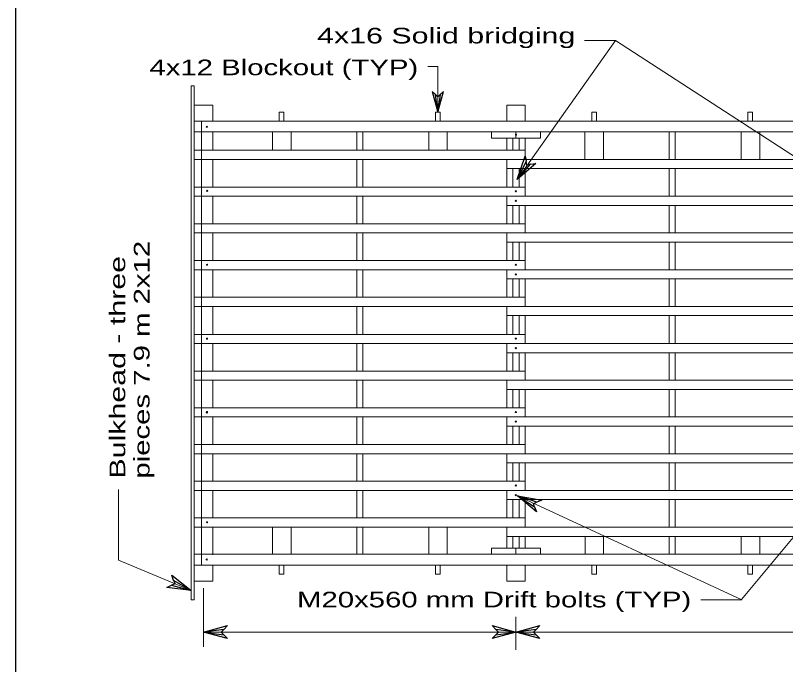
# Model space of a CAD drawing. Extents: x 13426 to 15509, y -9298 to -5111.
# Drawn here: x 15181.1 to 15245.4, y -5476.4 to -5422.2 of the extents above; entities that cross this region are included whole.
import ezdxf
from ezdxf.enums import TextEntityAlignment as Align

# ---------------------------------------------------------------- set-up
doc = ezdxf.new("R2010")
doc.units = 0
doc.header["$LTSCALE"] = 0.52
for name, color, linetype, lineweight in [('1', 7, 'Continuous', 13), ('15', 7, 'Continuous', 13), ('16', 7, 'Continuous', 25), ('2', 7, 'Continuous', 25), ('20', 7, 'Continuous', 13), ('3', 7, 'Continuous', 25), ('30', 7, 'Continuous', 25), ('4', 7, 'Continuous', 13), ('5', 7, 'Continuous', 25), ('6', 7, 'Continuous', 13)]:
    doc.layers.add(name, color=color, linetype=linetype, lineweight=lineweight)
doc.layers.add('19', color=7, linetype='Continuous')

msp = doc.modelspace()

# ---------------------------------------------------------------- linework, layer by layer
at = {"layer": '1'}
for p, q in [((15196.054, -5429.698), (15197.588, -5429.698)), ((15197.588, -5431.049), (15197.588, -5429.698)), ((15222.133, -5431.049), (15222.133, -5429.698)), ((15203.149, -5430.288), (15203.533, -5430.288)), ((15203.149, -5430.288), (15203.149, -5431.05)), ((15203.533, -5430.288), (15203.533, -5431.05)), ((15216.189, -5430.288), (15216.572, -5430.288)), ((15216.189, -5430.288), (15216.189, -5431.05)), ((15216.572, -5430.288), (15216.572, -5431.05)), ((15229.229, -5430.288), (15229.612, -5430.288)), ((15229.229, -5430.288), (15229.229, -5431.05)), ((15229.612, -5430.288), (15229.612, -5431.05)), ((15242.268, -5430.288), (15242.651, -5430.288)), ((15242.268, -5430.288), (15242.268, -5431.05)), ((15242.651, -5430.288), (15242.651, -5431.05)), ((15314.177, -5431.05), (15196.054, -5431.05)), ((15314.177, -5431.944), (15196.054, -5431.944)), ((15197.588, -5431.944), (15197.588, -5433.478)), ((15222.133, -5432.458), (15222.133, -5433.478)), ((15223.667, -5432.458), (15223.667, -5434.245)), ((15197.588, -5434.245), (15197.588, -5436.546)), ((15222.133, -5434.245), (15222.133, -5436.546)), ((15223.667, -5435.012), (15223.667, -5437.313)), ((15197.588, -5437.313), (15197.588, -5439.614)), ((15222.133, -5437.313), (15222.133, -5439.614)), ((15223.667, -5438.08), (15223.667, -5440.381)), ((15197.588, -5440.381), (15197.588, -5442.682)), ((15222.133, -5440.381), (15222.133, -5442.682)), ((15223.667, -5441.148), (15223.667, -5443.45)), ((15197.588, -5443.45), (15197.588, -5445.751)), ((15222.133, -5443.45), (15222.133, -5445.751)), ((15223.667, -5444.217), (15223.667, -5446.518)), ((15197.588, -5446.518), (15197.588, -5448.817)), ((15222.133, -5446.518), (15222.133, -5448.851)), ((15223.667, -5447.285), (15223.667, -5449.618)), ((15197.588, -5449.618), (15197.588, -5451.919)), ((15222.133, -5449.618), (15222.133, -5451.919)), ((15223.667, -5450.385), (15223.667, -5452.686)), ((15197.588, -5452.686), (15197.588, -5454.987)), ((15222.133, -5452.686), (15222.133, -5454.987)), ((15223.667, -5453.453), (15223.667, -5455.754)), ((15197.588, -5455.754), (15197.588, -5458.055)), ((15222.133, -5455.754), (15222.133, -5458.055)), ((15223.667, -5456.521), (15223.667, -5458.822)), ((15197.588, -5458.822), (15197.588, -5461.123)), ((15222.133, -5458.822), (15222.133, -5461.123)), ((15223.667, -5459.589), (15223.667, -5461.89)), ((15197.588, -5461.89), (15197.588, -5464.191)), ((15222.133, -5461.89), (15222.133, -5464.191)), ((15223.667, -5462.657), (15223.667, -5464.958)), ((15197.588, -5464.958), (15197.588, -5467.258)), ((15222.133, -5464.958), (15222.133, -5466.746)), ((15223.667, -5465.725), (15223.667, -5466.746)), ((15314.177, -5467.226), (15196.054, -5467.226)), ((15314.177, -5468.12), (15196.054, -5468.12)), ((15197.588, -5469.462), (15197.588, -5468.12)), ((15203.149, -5468.878), (15203.149, -5468.12)), ((15203.533, -5468.878), (15203.533, -5468.12)), ((15216.189, -5468.878), (15216.189, -5468.12)), ((15216.572, -5468.878), (15216.572, -5468.12)), ((15222.133, -5469.462), (15222.133, -5468.12)), ((15223.667, -5469.462), (15223.667, -5468.12)), ((15229.229, -5468.878), (15229.229, -5468.12)), ((15229.612, -5468.878), (15229.612, -5468.12)), ((15242.268, -5468.878), (15242.268, -5468.12)), ((15242.651, -5468.878), (15242.651, -5468.12)), ((15203.149, -5468.878), (15203.533, -5468.878)), ((15216.572, -5468.878), (15216.189, -5468.878)), ((15229.612, -5468.878), (15229.229, -5468.878)), ((15242.651, -5468.878), (15242.268, -5468.878)), ((15197.588, -5469.462), (15196.054, -5469.462)), ((15223.667, -5469.462), (15222.133, -5469.462))]:
    msp.add_line(p, q, dxfattribs=at)
msp.add_lwpolyline([(15223.667, -5431.049), (15223.667, -5429.698), (15222.133, -5429.698)], dxfattribs=at)
at = {"layer": '15'}
for p, q in [((15231.205, -5424.302), (15248.989, -5435.844)), ((15241.742, -5471.015), (15223.02, -5462.352)), ((15241.735, -5471.01), (15248.887, -5462.38)), ((15196.821, -5470.06), (15196.821, -5474.948)), ((15238.331, -5471.017), (15241.738, -5471.017)), ((15222.9, -5472.443), (15222.9, -5475.217)), ((15196.821, -5473.718), (15222.9, -5473.718))]:
    msp.add_line(p, q, dxfattribs=at)
for points in [[(15228.625, -5424.302), (15231.205, -5424.302), (15222.991, -5435.916)], [(15215.557, -5426.47), (15216.385, -5426.47), (15216.385, -5430.288)], [(15189.721, -5461.808), (15189.721, -5467.701), (15195.799, -5470.256)], [(15222.9, -5473.719), (15248.979, -5473.719), (15274.589, -5473.719)]]:
    msp.add_lwpolyline(points, dxfattribs=at)
at = {"layer": '16'}
for points in [[(15216.194, -5428.823), (15215.912, -5428.553), (15216.385, -5430.288), (15216.859, -5428.553), (15216.576, -5428.823), (15216.385, -5430.288), (15216.194, -5428.823), (15216.385, -5429.014), (15216.576, -5428.823)], [(15224.125, -5434.648), (15224.569, -5434.573), (15222.992, -5435.918), (15223.668, -5433.959), (15223.76, -5434.399), (15222.992, -5435.918), (15224.125, -5434.648), (15223.818, -5434.706), (15223.76, -5434.399)], [(15224.459, -5463.261), (15224.605, -5463.686), (15223.02, -5462.352), (15225.063, -5462.697), (15224.644, -5462.86), (15223.02, -5462.352), (15224.459, -5463.261), (15224.351, -5462.968), (15224.644, -5462.86)], [(15194.329, -5469.399), (15194.167, -5468.979), (15195.799, -5470.256), (15193.745, -5469.984), (15194.158, -5469.806), (15195.799, -5470.256), (15194.329, -5469.399), (15194.447, -5469.687), (15194.158, -5469.806)], [(15198.509, -5473.939), (15198.82, -5474.263), (15196.821, -5473.718), (15198.82, -5473.173), (15198.509, -5473.497), (15196.821, -5473.718), (15198.509, -5473.939), (15198.288, -5473.718), (15198.509, -5473.497)], [(15221.213, -5473.497), (15220.902, -5473.173), (15222.9, -5473.718), (15220.902, -5474.263), (15221.213, -5473.939), (15222.9, -5473.718), (15221.213, -5473.497), (15221.434, -5473.718), (15221.213, -5473.939)], [(15224.588, -5473.94), (15224.899, -5474.264), (15222.9, -5473.719), (15224.899, -5473.173), (15224.588, -5473.498), (15222.9, -5473.719), (15224.588, -5473.94), (15224.367, -5473.719), (15224.588, -5473.498)]]:
    msp.add_lwpolyline(points, dxfattribs=at)
at = {"layer": '2', "lineweight": 13}
for p, q in [((15196.054, -5428.084), (15195.799, -5428.084)), ((15195.799, -5428.084), (15195.799, -5471.037)), ((15196.054, -5428.084), (15196.054, -5471.037)), ((15223.667, -5433.478), (15196.054, -5433.478)), ((15224.568, -5434.245), (15196.054, -5434.245)), ((15276.725, -5434.245), (15222.133, -5434.245)), ((15249.746, -5435.012), (15222.133, -5435.012)), ((15225.315, -5435.012), (15222.133, -5435.012)), ((15223.667, -5436.546), (15196.054, -5436.546)), ((15223.667, -5437.313), (15196.054, -5437.313)), ((15279.436, -5437.314), (15222.133, -5437.314)), ((15249.746, -5438.081), (15222.133, -5438.081)), ((15223.667, -5439.614), (15196.054, -5439.614)), ((15223.667, -5440.381), (15196.054, -5440.381)), ((15281.086, -5440.382), (15222.133, -5440.382)), ((15249.746, -5441.149), (15222.133, -5441.149)), ((15223.667, -5442.682), (15196.054, -5442.682)), ((15223.667, -5443.45), (15196.054, -5443.45)), ((15282.504, -5443.45), (15222.133, -5443.45)), ((15249.746, -5444.217), (15222.133, -5444.217)), ((15223.667, -5445.751), (15196.054, -5445.751)), ((15223.667, -5446.518), (15196.054, -5446.518)), ((15283.906, -5446.518), (15222.133, -5446.518)), ((15249.746, -5447.285), (15222.133, -5447.285)), ((15223.667, -5448.851), (15196.054, -5448.851)), ((15224.568, -5449.618), (15196.054, -5449.618)), ((15284.726, -5449.618), (15222.133, -5449.618)), ((15249.746, -5450.385), (15222.133, -5450.385)), ((15225.315, -5450.385), (15222.133, -5450.385)), ((15223.667, -5451.919), (15196.054, -5451.919)), ((15223.667, -5452.686), (15196.054, -5452.686)), ((15285.606, -5452.686), (15222.133, -5452.686)), ((15249.746, -5453.453), (15222.133, -5453.453)), ((15223.667, -5454.987), (15196.054, -5454.987)), ((15223.667, -5455.754), (15196.054, -5455.754)), ((15286.539, -5455.754), (15222.133, -5455.754)), ((15249.746, -5456.521), (15222.133, -5456.521)), ((15223.667, -5458.055), (15196.054, -5458.055)), ((15223.667, -5458.822), (15196.054, -5458.822)), ((15287.474, -5458.822), (15222.133, -5458.822)), ((15249.746, -5459.59), (15222.133, -5459.59)), ((15223.667, -5461.123), (15196.054, -5461.123)), ((15223.667, -5461.89), (15196.054, -5461.89)), ((15288.397, -5461.891), (15222.133, -5461.891)), ((15249.746, -5462.658), (15222.133, -5462.658)), ((15223.667, -5464.191), (15196.054, -5464.191)), ((15223.667, -5464.958), (15196.054, -5464.958)), ((15288.709, -5464.959), (15222.133, -5464.959)), ((15249.746, -5465.726), (15222.133, -5465.726)), ((15196.054, -5471.037), (15195.799, -5471.037))]:
    msp.add_line(p, q, dxfattribs=at)
at = {"layer": '3', "lineweight": 13}
for p, q in [((15222.9, -5432.458), (15222.9, -5431.944)), ((15224.946, -5432.458), (15224.946, -5431.946)), ((15224.946, -5432.458), (15222.9, -5432.458)), ((15220.855, -5466.714), (15222.9, -5466.714)), ((15220.855, -5466.714), (15220.855, -5467.225)), ((15222.9, -5466.714), (15224.946, -5466.714)), ((15222.9, -5466.714), (15222.9, -5467.225)), ((15224.946, -5466.714), (15224.946, -5467.225))]:
    msp.add_line(p, q, dxfattribs=at)
msp.add_lwpolyline([(15222.9, -5432.458), (15220.855, -5432.458), (15220.855, -5431.946)], dxfattribs=at)
at = {"layer": '30'}
msp.add_line((15181.119, -5379.846), (15181.119, -5592.065), dxfattribs=at)
at = {"layer": '4'}
for p, q in [((15196.645, -5431.05), (15196.645, -5468.12)), ((15209.605, -5433.477), (15209.605, -5431.943)), ((15210.117, -5433.477), (15210.117, -5431.943)), ((15235.684, -5431.944), (15235.684, -5434.243)), ((15236.196, -5431.944), (15236.196, -5434.243)), ((15222.645, -5432.458), (15222.645, -5433.478)), ((15223.156, -5432.458), (15223.156, -5433.478)), ((15209.605, -5434.245), (15209.605, -5436.545)), ((15210.117, -5434.245), (15210.117, -5436.545)), ((15222.645, -5435.012), (15222.645, -5436.546)), ((15223.156, -5435.012), (15223.156, -5436.546)), ((15235.684, -5437.312), (15235.684, -5435.01)), ((15236.196, -5437.312), (15236.196, -5435.01)), ((15209.605, -5437.312), (15209.605, -5439.613)), ((15210.117, -5437.312), (15210.117, -5439.613)), ((15222.645, -5438.08), (15222.645, -5439.614)), ((15223.156, -5438.08), (15223.156, -5439.614)), ((15235.684, -5440.38), (15235.684, -5438.079)), ((15236.196, -5440.38), (15236.196, -5438.079)), ((15209.605, -5440.38), (15209.605, -5442.681)), ((15210.117, -5440.38), (15210.117, -5442.681)), ((15222.645, -5441.148), (15222.645, -5442.682)), ((15223.156, -5441.148), (15223.156, -5442.682)), ((15235.684, -5443.447), (15235.684, -5441.147)), ((15236.196, -5443.447), (15236.196, -5441.147)), ((15209.605, -5443.448), (15209.605, -5445.75)), ((15210.117, -5443.448), (15210.117, -5445.75)), ((15222.645, -5444.217), (15222.645, -5445.751)), ((15223.156, -5444.217), (15223.156, -5445.751)), ((15235.684, -5446.516), (15235.684, -5444.217)), ((15236.196, -5446.516), (15236.196, -5444.217)), ((15209.605, -5448.851), (15209.605, -5446.516)), ((15210.117, -5448.851), (15210.117, -5446.516)), ((15222.645, -5447.285), (15222.645, -5448.851)), ((15223.156, -5447.285), (15223.156, -5448.851)), ((15235.684, -5449.584), (15235.684, -5447.285)), ((15236.196, -5449.584), (15236.196, -5447.285)), ((15209.605, -5449.616), (15209.605, -5451.918)), ((15210.117, -5449.616), (15210.117, -5451.918)), ((15222.645, -5450.385), (15222.645, -5451.919)), ((15223.156, -5450.385), (15223.156, -5451.919)), ((15235.684, -5452.684), (15235.684, -5450.385)), ((15236.196, -5452.684), (15236.196, -5450.385)), ((15209.605, -5452.685), (15209.605, -5454.986)), ((15210.117, -5452.685), (15210.117, -5454.986)), ((15222.645, -5453.453), (15222.645, -5454.987)), ((15223.156, -5453.453), (15223.156, -5454.987)), ((15235.684, -5455.752), (15235.684, -5453.451)), ((15236.196, -5455.752), (15236.196, -5453.451)), ((15209.605, -5455.753), (15209.605, -5458.054)), ((15210.117, -5455.753), (15210.117, -5458.054)), ((15222.645, -5456.521), (15222.645, -5458.055)), ((15223.156, -5456.521), (15223.156, -5458.055)), ((15235.684, -5458.82), (15235.684, -5456.519)), ((15236.196, -5458.82), (15236.196, -5456.519)), ((15209.605, -5458.821), (15209.605, -5461.122)), ((15210.117, -5458.821), (15210.117, -5461.122)), ((15222.645, -5459.589), (15222.645, -5461.123)), ((15223.156, -5459.589), (15223.156, -5461.123)), ((15235.684, -5461.888), (15235.684, -5459.587)), ((15236.196, -5461.888), (15236.196, -5459.587)), ((15209.605, -5461.889), (15209.605, -5464.19)), ((15210.117, -5461.889), (15210.117, -5464.19)), ((15222.645, -5462.657), (15222.645, -5464.191)), ((15223.156, -5462.657), (15223.156, -5464.191)), ((15235.684, -5464.956), (15235.684, -5462.655)), ((15236.196, -5464.956), (15236.196, -5462.655)), ((15209.605, -5467.224), (15209.605, -5464.957)), ((15210.117, -5467.224), (15210.117, -5464.957)), ((15222.645, -5465.725), (15222.645, -5466.746)), ((15223.156, -5465.725), (15223.156, -5466.746)), ((15235.684, -5465.723), (15235.684, -5467.226)), ((15236.196, -5465.723), (15236.196, -5467.226))]:
    msp.add_line(p, q, dxfattribs=at)
at = {"layer": '5', "lineweight": 13}
for p, q in [((15202.588, -5433.478), (15202.588, -5431.946)), ((15204.127, -5433.478), (15204.127, -5431.946)), ((15215.627, -5433.478), (15215.627, -5431.944)), ((15217.167, -5433.478), (15217.167, -5431.944)), ((15228.663, -5434.242), (15228.663, -5431.943)), ((15230.203, -5434.242), (15230.203, -5431.943)), ((15241.708, -5434.245), (15241.708, -5431.944)), ((15243.247, -5434.245), (15243.247, -5431.944)), ((15202.588, -5467.224), (15202.588, -5464.958)), ((15204.128, -5467.224), (15204.128, -5464.958)), ((15215.628, -5467.226), (15215.628, -5464.958)), ((15217.168, -5467.226), (15217.168, -5464.958)), ((15228.671, -5467.227), (15228.671, -5465.726)), ((15230.21, -5467.226), (15230.21, -5465.726)), ((15241.707, -5467.226), (15241.707, -5465.726)), ((15243.247, -5467.226), (15243.247, -5465.726))]:
    msp.add_line(p, q, dxfattribs=at)
at = {"layer": '6'}
for centre in [(15197.1023, -5431.5102), (15222.9003, -5432.1699), (15197.1215, -5436.8664), (15222.8875, -5436.9023), (15222.8933, -5437.7036), (15197.1158, -5443.0385), (15222.8875, -5443.0385), (15222.8933, -5443.8398), (15197.1158, -5449.2067), (15222.8875, -5449.2067), (15222.8933, -5450.008), (15197.0994, -5455.3783), (15197.1158, -5455.3429), (15222.8875, -5455.3429), (15222.8933, -5456.1442), (15222.8875, -5461.4791), (15222.8933, -5462.2804), (15197.1158, -5464.5472), (15197.0883, -5467.6567)]:
    msp.add_circle(centre, 0.0479, dxfattribs=at)

# ---------------------------------------------------------------- texts
at = {"layer": '19'}
for s, width, p in [('pieces 7.9 m 2x12', 1.4, (15192.313, -5460.9)), ('Bulkhead - three', 1.45, (15190.285, -5460.9))]:
    msp.add_text(s, height=1.307, rotation=90, dxfattribs=dict(at, width=width)).set_placement(p)
at = {"layer": '19', "width": 1.4}
msp.add_text('M20x560 mm Drift bolts (TYP)', height=1.307, dxfattribs=at).set_placement((15237.532, -5471.658), align=Align.RIGHT)
at = {"layer": '20'}
for s, width, p in [('4x16 Solid bridging', 1.45, (15227.856, -5424.552)), ('4x12 Blockout (TYP)', 1.4, (15214.744, -5427.207))]:
    msp.add_text(s, height=1.307, dxfattribs=dict(at, width=width)).set_placement(p, align=Align.RIGHT)

doc.saveas('drawing.dxf')
